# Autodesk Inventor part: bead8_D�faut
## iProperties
Created: 2011-01
Part Number: bead8_D�faut
Document SubType Name: Modeling
Designer: eric
Density: 1 g/cm^3
Mass: 0.24495 g
Surface Area: 6.79212 cm^2
Volume: 0.24495 cm^3
Author: eric
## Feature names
1. Base1
